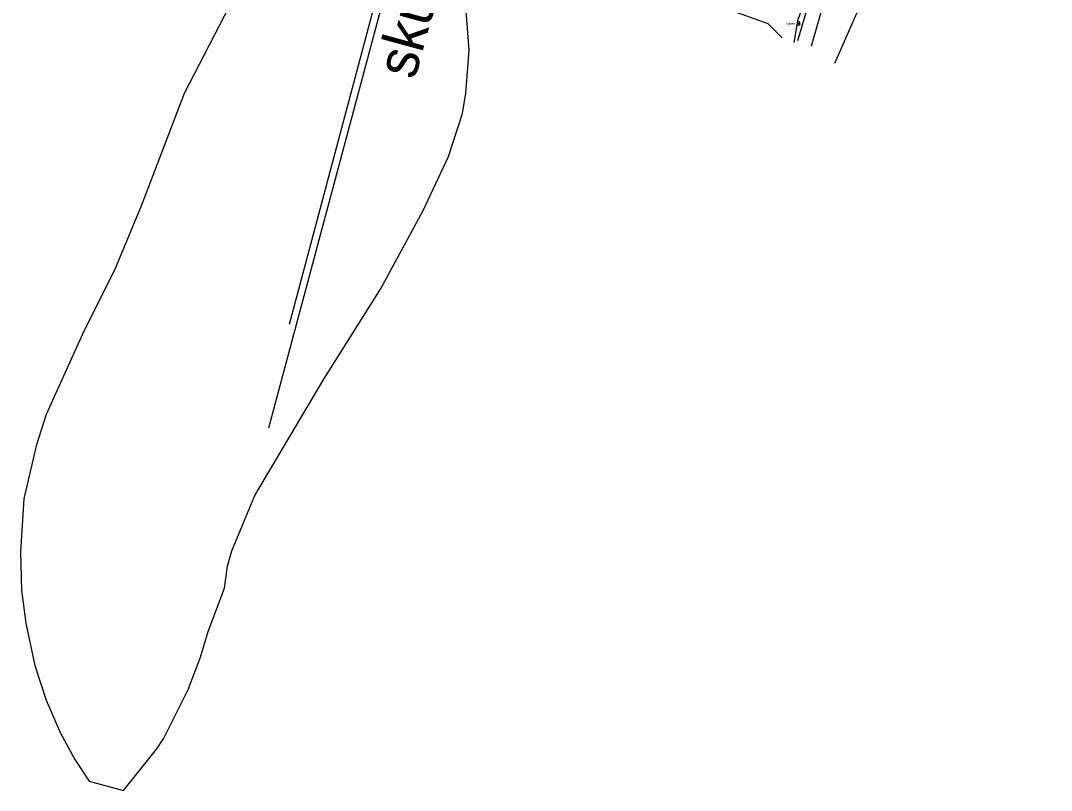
# Model space of a CAD drawing. Extents: x -555887 to -552101, y -1100251 to -1096546.
# Drawn here: x -554177.7 to -553801.9, y -1099017.1 to -1098736.4 of the extents above; entities that cross this region are included whole.
import ezdxf

# ---------------------------------------------------------------- set-up
doc = ezdxf.new("R2010")
doc.units = 0
for name, color, linetype in [('07_KANALIZACE', 7, 'Continuous'), ('07_VODOVOD', 7, 'Continuous'), ('vrstevnice', 7, 'Continuous'), ('ZSST', 7, 'Continuous')]:
    doc.layers.add(name, color=color, linetype=linetype)

msp = doc.modelspace()

# ---------------------------------------------------------------- linework, layer by layer
at = {"layer": '07_KANALIZACE'}
msp.add_lwpolyline([(-554087.21, -1098884.94), (-554044.09, -1098723.55), (-553946.28, -1098356.13), (-553945.28, -1098350.61), (-553945.11, -1098348.21), (-553937.04, -1098317.66), (-553932.95, -1098309.77), (-553933.89, -1098299.13), (-553960.89, -1098094.71)], dxfattribs=at)
at = {"layer": '07_VODOVOD'}
msp.add_lwpolyline([(-554079.66, -1098847.14), (-553997.7, -1098539.18), (-553945.85, -1098344.3), (-553938.25, -1098317.52), (-553935.78, -1098308.01), (-553936.18, -1098296.39), (-554003.21, -1097797.26)], dxfattribs=at)
at = {"layer": 'vrstevnice'}
msp.add_lwpolyline([(-554096.25, -1098720.54), (-554118.02, -1098762.95), (-554133.6, -1098803.67), (-554143.43, -1098827.4), (-554154.56, -1098849.38), (-554168.42, -1098880.06), (-554172.08, -1098891.43), (-554176.47, -1098910.77), (-554177.69, -1098930.05), (-554177.41, -1098944.09), (-554175.73, -1098956.16), (-554172.5, -1098971.61), (-554168.42, -1098984.25), (-554163.23, -1098996.04), (-554157.89, -1099005.87), (-554152.7, -1099013.73), (-554140.2, -1099017.1), (-554127.98, -1099001.94), (-554125.46, -1098998.01), (-554116.61, -1098980.31), (-554112.12, -1098968.52), (-554109.31, -1098959.11), (-554103.41, -1098943.38), (-554102.29, -1098935.38), (-554100.74, -1098929.76), (-554092.32, -1098909.54), (-554067.19, -1098867.14), (-554046.54, -1098834.28), (-554030.96, -1098805.64), (-554021.69, -1098785.98), (-554016.64, -1098770.25), (-554015.37, -1098762.81), (-554014.11, -1098747.22), (-554015.37, -1098731.22)], dxfattribs=at)
at = {"layer": 'ZSST'}
for points in [[(-553889.35, -1098745.65), (-553882.93, -1098723.13), (-553875.04, -1098698.54), (-553869.21, -1098680.04), (-553864.88, -1098666.8), (-553856.74, -1098642.76), (-553849.22, -1098619.35), (-553841.56, -1098593.48), (-553832.4, -1098566.45), (-553824.87, -1098540.95), (-553819.91, -1098526.76), (-553817.36, -1098516.81), (-553817.35, -1098516.78), (-553817.25, -1098499.54), (-553817.67, -1098480.13), (-553816.77, -1098462.81), (-553816.62, -1098441.06), (-553816.2, -1098418.53), (-553814.67, -1098393.91), (-553817.77, -1098360.56), (-553817.74, -1098360.46), (-553822.42, -1098341.11), (-553828.7, -1098326), (-553834.9, -1098309.92)], [(-553880.92, -1098751.91), (-553871.84, -1098731.55), (-553872.8, -1098722.24), (-553869.81, -1098704.03), (-553861.5, -1098678.92), (-553860.1, -1098662.53), (-553850.24, -1098632.89), (-553840.23, -1098613.91), (-553836.69, -1098605.08), (-553832.74, -1098577), (-553823.82, -1098550.82), (-553817.23, -1098534.33), (-553810.62, -1098531.16), (-553801.92, -1098529.52), (-553802.46, -1098510.5), (-553808.13, -1098504.83), (-553803.98, -1098489.56), (-553808.05, -1098471.62), (-553809.34, -1098447.1), (-553811.49, -1098417.06), (-553812.01, -1098398.44), (-553812.41, -1098374.99), (-553814.7, -1098350.02), (-553816.16, -1098339.34)], [(-553895.65, -1098744.45), (-553894.22, -1098735.87), (-553885.5, -1098713.24), (-553884.3, -1098704.98), (-553878.65, -1098690.58), (-553872.62, -1098670.76), (-553863.14, -1098645.17), (-553854.12, -1098617.37), (-553842.45, -1098580.09), (-553830.41, -1098541.86), (-553825.12, -1098516.11), (-553823.29, -1098496.4), (-553822.97, -1098469.34), (-553823.13, -1098428.02), (-553823.34, -1098400.78), (-553822.41, -1098378.86), (-553824.25, -1098360.4), (-553828.68, -1098347.72), (-553841.43, -1098347.33)], [(-553894.35, -1098743.63), (-553890.92, -1098732.27), (-553885.5, -1098713.24), (-553881.29, -1098701.55), (-553877.07, -1098690.4), (-553871.37, -1098671.33), (-553863.14, -1098645.17)], [(-553900.09, -1098742.67), (-553905.22, -1098737.61), (-553928.92, -1098729.13), (-553969.26, -1098715.99), (-554003.17, -1098706.15), (-554027.46, -1098699.56), (-554045.32, -1098695.47), (-554049.11, -1098696.22), (-554051.22, -1098698.39)]]:
    msp.add_lwpolyline(points, dxfattribs=at)
for radius in [0.5, 0.0327]:
    msp.add_circle((-553894.14, -1098737.71), radius, dxfattribs=at)
msp.add_arc((-553894.14, -1098737.25), 0.5, 331.7891, 208.7844, dxfattribs=at)

# ---------------------------------------------------------------- texts
at = {"layer": '07_VODOVOD'}
msp.add_text('skupinový vodovod SOMU - sever', height=15, rotation=74.7137, dxfattribs=at).set_placement((-554034.02, -1098758.24))
at = {"layer": 'ZSST'}
msp.add_text('kámen', height=0.75, dxfattribs=at).set_placement((-553898.46, -1098737.86))

doc.saveas('drawing.dxf')
